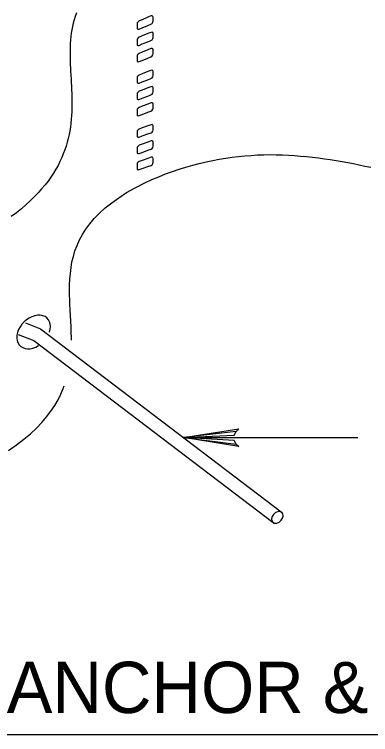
# Model space of a CAD drawing. Extents: x 638850 to 644908, y 297188 to 298900.
# Drawn here: x 639003.7 to 639035, y 297879.4 to 297942.6 of the extents above; entities that cross this region are included whole.
import ezdxf

# ---------------------------------------------------------------- set-up
doc = ezdxf.new("R2010")
doc.units = 0
for name, color, linetype in [('1', 7, 'Continuous'), ('16', 7, 'Continuous'), ('2', 7, 'Continuous'), ('4', 7, 'Continuous'), ('7', 7, 'Continuous')]:
    doc.layers.add(name, color=color, linetype=linetype)

msp = doc.modelspace()

# ---------------------------------------------------------------- linework, layer by layer
at = {"layer": '1'}
for p, q in [((639004.699, 297915.501), (639006.018, 297914.995)), ((639006.018, 297914.995), (639027.272, 297898.836)), ((639004.073, 297914.478), (639005.437, 297913.954)), ((639005.437, 297913.954), (639026.558, 297897.897))]:
    msp.add_line(p, q, dxfattribs=at)
msp.add_lwpolyline([(639023.205, 297904.856), (639023.033, 297905.19), (639018.592, 297905.435), (639023.205, 297904.856), (639023.441, 297904.654), (639018.592, 297905.435), (639023.029, 297905.655), (639023.191, 297905.985), (639018.592, 297905.435), (639023.441, 297906.206), (639023.191, 297905.985)], dxfattribs=at)
for centre, major_axis, start_param in [((639005.426, 297914.706), (-1.203, -1.196), 2.18443), ((639026.818, 297898.436), (-0.416, -0.414), 1.264481)]:
    msp.add_ellipse(centre, major_axis=major_axis, ratio=0.717222, start_param=start_param, end_param=7.533439, dxfattribs=at)
at = {"layer": '16'}
for points in [[(639015.725, 297941.734), (639015.833, 297941.796), (639015.895, 297941.888), (639015.925, 297941.996), (639015.925, 297941.996), (639015.925, 297942.088), (639015.925, 297942.241), (639015.925, 297942.336), (639015.925, 297942.336), (639015.895, 297942.412), (639015.833, 297942.46), (639015.725, 297942.444), (639015.725, 297942.444), (639015.46, 297942.336), (639014.953, 297942.12), (639014.688, 297942.012), (639014.688, 297942.012), (639014.596, 297941.934), (639014.518, 297941.842), (639014.504, 297941.734), (639014.504, 297941.734), (639014.504, 297941.656), (639014.504, 297941.485), (639014.504, 297941.41), (639014.504, 297941.41), (639014.518, 297941.315), (639014.596, 297941.286), (639014.688, 297941.302), (639014.688, 297941.302), (639014.953, 297941.41), (639015.46, 297941.61), (639015.725, 297941.734), (639015.725, 297941.734), (639015.725, 297941.734)], [(639015.725, 297940.297), (639015.833, 297940.36), (639015.895, 297940.468), (639015.925, 297940.559), (639015.925, 297940.559), (639015.925, 297940.651), (639015.925, 297940.805), (639015.925, 297940.9), (639015.925, 297940.9), (639015.895, 297940.991), (639015.833, 297941.024), (639015.725, 297941.008), (639015.725, 297941.008), (639015.46, 297940.9), (639014.953, 297940.697), (639014.688, 297940.589), (639014.688, 297940.589), (639014.596, 297940.513), (639014.518, 297940.419), (639014.504, 297940.311), (639014.504, 297940.311), (639014.504, 297940.235), (639014.504, 297940.065), (639014.504, 297939.987), (639014.504, 297939.987), (639014.518, 297939.895), (639014.596, 297939.865), (639014.688, 297939.865), (639014.688, 297939.865), (639014.953, 297939.987), (639015.46, 297940.189), (639015.725, 297940.297), (639015.725, 297940.297), (639015.725, 297940.297)], [(639015.725, 297938.861), (639015.833, 297938.937), (639015.895, 297939.031), (639015.925, 297939.139), (639015.925, 297939.139), (639015.925, 297939.215), (639015.925, 297939.385), (639015.925, 297939.463), (639015.925, 297939.463), (639015.895, 297939.555), (639015.833, 297939.601), (639015.725, 297939.587), (639015.725, 297939.587), (639015.46, 297939.479), (639014.953, 297939.261), (639014.688, 297939.153), (639014.688, 297939.153), (639014.596, 297939.093), (639014.518, 297938.999), (639014.504, 297938.891), (639014.504, 297938.891), (639014.504, 297938.815), (639014.504, 297938.645), (639014.504, 297938.567), (639014.504, 297938.567), (639014.518, 297938.475), (639014.596, 297938.429), (639014.688, 297938.443), (639014.688, 297938.443), (639014.953, 297938.551), (639015.46, 297938.753), (639015.725, 297938.861), (639015.725, 297938.861), (639015.725, 297938.861)], [(639015.725, 297936.96), (639015.833, 297937.022), (639015.895, 297937.114), (639015.925, 297937.222), (639015.925, 297937.222), (639015.925, 297937.317), (639015.925, 297937.471), (639015.925, 297937.562), (639015.925, 297937.562), (639015.895, 297937.641), (639015.833, 297937.687), (639015.725, 297937.67), (639015.725, 297937.67), (639015.46, 297937.562), (639014.953, 297937.363), (639014.688, 297937.255), (639014.688, 297937.255), (639014.596, 297937.192), (639014.518, 297937.101), (639014.504, 297936.993), (639014.504, 297936.993), (639014.504, 297936.914), (639014.504, 297936.744), (639014.504, 297936.669), (639014.504, 297936.669), (639014.518, 297936.574), (639014.596, 297936.544), (639014.688, 297936.544), (639014.688, 297936.544), (639014.953, 297936.652), (639015.46, 297936.852), (639015.725, 297936.96), (639015.725, 297936.96), (639015.725, 297936.96)], [(639015.725, 297935.524), (639015.833, 297935.586), (639015.895, 297935.678), (639015.925, 297935.786), (639015.925, 297935.786), (639015.925, 297935.88), (639015.925, 297936.034), (639015.925, 297936.126), (639015.925, 297936.126), (639015.895, 297936.204), (639015.833, 297936.25), (639015.725, 297936.234), (639015.725, 297936.234), (639015.46, 297936.142), (639014.953, 297935.942), (639014.688, 297935.834), (639014.688, 297935.834), (639014.596, 297935.772), (639014.518, 297935.678), (639014.504, 297935.57), (639014.504, 297935.57), (639014.504, 297935.494), (639014.504, 297935.324), (639014.504, 297935.246), (639014.504, 297935.246), (639014.518, 297935.154), (639014.596, 297935.108), (639014.688, 297935.124), (639014.688, 297935.124), (639014.953, 297935.232), (639015.46, 297935.416), (639015.725, 297935.524), (639015.725, 297935.524), (639015.725, 297935.524)], [(639015.725, 297934.104), (639015.833, 297934.166), (639015.895, 297934.258), (639015.925, 297934.366), (639015.925, 297934.366), (639015.925, 297934.444), (639015.925, 297934.614), (639015.925, 297934.69), (639015.925, 297934.69), (639015.895, 297934.784), (639015.833, 297934.83), (639015.725, 297934.814), (639015.725, 297934.814), (639015.46, 297934.706), (639014.953, 297934.519), (639014.688, 297934.411), (639014.688, 297934.411), (639014.596, 297934.352), (639014.518, 297934.258), (639014.504, 297934.15), (639014.504, 297934.15), (639014.504, 297934.074), (639014.504, 297933.904), (639014.504, 297933.826), (639014.504, 297933.826), (639014.518, 297933.734), (639014.596, 297933.688), (639014.688, 297933.701), (639014.688, 297933.701), (639014.953, 297933.809), (639015.46, 297933.996), (639015.725, 297934.104), (639015.725, 297934.104), (639015.725, 297934.104)], [(639015.738, 297932.189), (639015.833, 297932.251), (639015.895, 297932.343), (639015.925, 297932.451), (639015.925, 297932.451), (639015.925, 297932.543), (639015.925, 297932.697), (639015.925, 297932.791), (639015.925, 297932.791), (639015.895, 297932.867), (639015.833, 297932.916), (639015.738, 297932.899), (639015.738, 297932.899), (639015.46, 297932.808), (639014.953, 297932.621), (639014.688, 297932.513), (639014.688, 297932.513), (639014.596, 297932.451), (639014.518, 297932.359), (639014.504, 297932.251), (639014.504, 297932.251), (639014.504, 297932.173), (639014.504, 297932.019), (639014.504, 297931.925), (639014.504, 297931.925), (639014.518, 297931.833), (639014.596, 297931.803), (639014.688, 297931.803), (639014.688, 297931.803), (639014.953, 297931.911), (639015.46, 297932.095), (639015.738, 297932.189), (639015.738, 297932.189), (639015.738, 297932.189)], [(639015.738, 297930.753), (639015.833, 297930.815), (639015.895, 297930.907), (639015.925, 297931.015), (639015.925, 297931.015), (639015.925, 297931.107), (639015.925, 297931.263), (639015.925, 297931.355), (639015.925, 297931.355), (639015.895, 297931.447), (639015.833, 297931.479), (639015.738, 297931.479), (639015.738, 297931.479), (639015.46, 297931.371), (639014.953, 297931.201), (639014.688, 297931.093), (639014.688, 297931.093), (639014.596, 297931.031), (639014.518, 297930.937), (639014.504, 297930.829), (639014.504, 297930.829), (639014.504, 297930.753), (639014.504, 297930.583), (639014.504, 297930.505), (639014.504, 297930.505), (639014.518, 297930.413), (639014.596, 297930.38), (639014.688, 297930.38), (639014.688, 297930.38), (639014.953, 297930.475), (639015.46, 297930.658), (639015.738, 297930.753), (639015.738, 297930.753), (639015.738, 297930.753)], [(639015.738, 297929.333), (639015.833, 297929.392), (639015.895, 297929.487), (639015.925, 297929.595), (639015.925, 297929.595), (639015.925, 297929.67), (639015.925, 297929.84), (639015.925, 297929.919), (639015.925, 297929.919), (639015.895, 297930.01), (639015.833, 297930.056), (639015.738, 297930.043), (639015.738, 297930.043), (639015.46, 297929.948), (639014.953, 297929.765), (639014.688, 297929.67), (639014.688, 297929.67), (639014.596, 297929.608), (639014.518, 297929.516), (639014.504, 297929.408), (639014.504, 297929.408), (639014.504, 297929.333), (639014.504, 297929.163), (639014.504, 297929.084), (639014.504, 297929.084), (639014.518, 297928.993), (639014.596, 297928.947), (639014.688, 297928.96), (639014.688, 297928.96), (639014.953, 297929.055), (639015.46, 297929.238), (639015.738, 297929.333), (639015.738, 297929.333), (639015.738, 297929.333)]]:
    msp.add_lwpolyline(points, dxfattribs=at)
at = {"layer": '2'}
for points in [[(639009.176, 297942.708), (639009.068, 297942.413), (639008.975, 297942.12), (639008.897, 297941.826), (639008.836, 297941.533), (639008.773, 297941.241), (639008.728, 297940.93), (639008.696, 297940.638), (639008.665, 297940.345), (639008.636, 297940.035), (639008.636, 297939.726), (639008.622, 297939.418), (639008.622, 297939.123), (639008.622, 297938.815), (639008.636, 297938.505), (639008.636, 297938.181), (639008.651, 297937.875), (639008.665, 297937.564), (639008.681, 297937.24), (639008.71, 297936.932), (639008.728, 297936.608), (639008.744, 297936.297), (639008.759, 297935.973), (639008.773, 297935.649), (639008.773, 297935.325), (639008.789, 297935.001), (639008.789, 297934.675), (639008.773, 297934.353), (639008.773, 297934.029), (639008.759, 297933.703), (639008.728, 297933.361), (639008.696, 297933.042), (639008.651, 297932.7), (639008.606, 297932.373), (639008.543, 297932.034), (639008.465, 297931.696), (639008.372, 297931.372), (639008.278, 297931.03), (639008.156, 297930.693), (639008.033, 297930.351), (639007.893, 297930.011), (639007.738, 297929.671), (639007.571, 297929.334), (639007.369, 297928.994), (639007.169, 297928.654), (639006.937, 297928.296), (639006.692, 297927.957), (639006.426, 297927.619), (639006.131, 297927.264), (639005.825, 297926.922), (639005.483, 297926.582), (639005.128, 297926.229), (639004.759, 297925.889), (639004.358, 297925.531), (639003.926, 297925.178), (639003.463, 297924.838)], [(639008.606, 297917.116), (639008.575, 297918.349), (639008.588, 297918.86), (639008.606, 297919.355), (639008.651, 297919.848), (639008.71, 297920.358), (639008.789, 297920.853), (639008.912, 297921.333), (639009.054, 297921.828), (639009.236, 297922.305), (639009.457, 297922.784), (639009.716, 297923.263), (639010.01, 297923.742), (639010.366, 297924.204), (639010.753, 297924.667), (639011.216, 297925.131), (639011.711, 297925.594), (639012.281, 297926.042), (639012.899, 297926.49), (639013.592, 297926.94), (639014.351, 297927.372), (639015.183, 297927.804), (639015.183, 297927.804), (639015.802, 297928.08), (639016.403, 297928.326), (639017.006, 297928.578), (639017.611, 297928.791), (639018.209, 297928.994), (639018.799, 297929.176), (639019.4, 297929.347), (639019.969, 297929.505), (639020.558, 297929.642), (639021.143, 297929.766), (639021.717, 297929.874), (639022.286, 297929.966), (639022.842, 297930.045), (639023.416, 297930.119), (639023.972, 297930.166), (639024.527, 297930.211), (639025.083, 297930.243), (639025.623, 297930.261), (639026.179, 297930.276), (639026.719, 297930.261), (639027.259, 297930.261), (639027.799, 297930.227), (639028.325, 297930.198), (639028.852, 297930.148), (639029.392, 297930.103), (639029.916, 297930.058), (639030.427, 297929.997), (639030.951, 297929.919), (639031.462, 297929.842), (639031.988, 297929.766), (639032.497, 297929.671), (639033.005, 297929.579), (639033.5, 297929.487), (639034.009, 297929.379), (639034.504, 297929.268), (639035.015, 297929.16)], [(639008.744, 297913.978), (639008.744, 297914.198), (639008.728, 297914.691), (639008.71, 297915.17), (639008.681, 297915.663), (639008.665, 297916.158), (639008.636, 297916.639), (639008.606, 297917.116)], [(639003.229, 297904.296), (639003.926, 297904.791), (639004.574, 297905.286), (639005.144, 297905.765), (639005.67, 297906.26), (639006.149, 297906.753), (639006.568, 297907.248), (639006.937, 297907.743), (639007.277, 297908.251), (639007.571, 297908.746), (639007.817, 297909.241), (639008.033, 297909.734), (639008.113, 297909.966)]]:
    msp.add_lwpolyline(points, dxfattribs=at)
at = {"layer": '4'}
msp.add_line((638963.538, 297879.366), (639114.909, 297879.366), dxfattribs=at)
at = {"layer": '7'}
msp.add_line((639018.592, 297905.435), (639033.89, 297905.435), dxfattribs=at)

# ---------------------------------------------------------------- texts
at = {"layer": '4'}
msp.add_text('J-PIN STAKE ANCHOR & TENDON DETAIL', height=4.5, dxfattribs=at).set_placement((638964.945, 297881.259))

doc.saveas('drawing.dxf')
